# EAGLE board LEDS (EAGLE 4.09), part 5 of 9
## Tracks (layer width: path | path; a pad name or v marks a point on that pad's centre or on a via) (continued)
N$X.358  (via drill 0.2)  (1 unrouted) (continued)
  Bottom 0.2: 115.32,46.92 115.87,46.37
  other vias: 115.92,46.28
N$X.359  (via drill 0.2)  (1 unrouted)
  Bottom 0.2: 56.79,39.04 57.33,38.49
  other vias: 57.39,38.4
N$X.360  (via drill 0.2)  (1 unrouted)
  Bottom 0.2: 55.06,39.04 55.6,38.49
  other vias: 55.66,38.4
N$X.361  (via drill 0.2)  (1 unrouted)
  Bottom 0.2: 53.24,39.08 53.78,38.54
  other vias: 53.84,38.44
N$X.362  (via drill 0.2)  (1 unrouted)
  Bottom 0.2: 51.39,39.08 51.94,38.54
  other vias: 51.99,38.44
N$X.363  (via drill 0.2)  (1 unrouted)
  Bottom 0.2: 49.62,39.08 50.16,38.54
  other vias: 50.22,38.44
N$X.364  (via drill 0.2)  (1 unrouted)
  Bottom 0.2: 47.84,39.13 48.39,38.58
  other vias: 48.44,38.49
N$X.365  (via drill 0.2)  (1 unrouted)
  Bottom 0.2: 45.98,39.06 46.52,38.51
  other vias: 46.57,38.42
N$X.366  (via drill 0.2)  (1 unrouted)
  Bottom 0.2: 44.22,39.04 44.77,38.49
  other vias: 44.82,38.4
N$X.367  (via drill 0.2)  (1 unrouted)
  Bottom 0.2: 40.67,36.38 41.22,35.84
  other vias: 41.27,35.75
N$X.368  (via drill 0.2)  (1 unrouted)
  Bottom 0.2: 42.38,36.47 42.92,35.93
  other vias: 42.98,35.84
N$X.369  (via drill 0.2)  (1 unrouted)
  Bottom 0.2: 44.22,36.47 44.77,35.93
  other vias: 44.82,35.84
N$X.370  (via drill 0.2)  (1 unrouted)
  Bottom 0.2: 45.98,36.43 46.52,35.88
  other vias: 46.57,35.79
N$X.371  (via drill 0.2)  (1 unrouted)
  Bottom 0.2: 47.82,36.41 48.37,35.86
  other vias: 48.42,35.77
N$X.372  (via drill 0.2)  (1 unrouted)
  Bottom 0.2: 49.59,36.43 50.14,35.88
  other vias: 50.19,35.79
N$X.373  (via drill 0.2)  (1 unrouted)
  Bottom 0.2: 51.39,36.45 51.94,35.91
  other vias: 51.99,35.81
N$X.374  (via drill 0.2)  (1 unrouted)
  Bottom 0.2: 53.21,36.45 53.76,35.91
  other vias: 53.81,35.81
N$X.375  (via drill 0.2)  (1 unrouted)
  Bottom 0.2: 98.04,33.18 97.41,33.81 97.38,33.81
  other vias: 98.02,33.19
N$X.376  (via drill 0.2)  (1 unrouted)
  Bottom 0.2: 98.02,35.83 97.38,36.46 97.22,36.46
  other vias: 98.03,35.85
N$X.377  (via drill 0.2)  (1 unrouted)
  Bottom 0.2: 98.09,38.48 97.53,39.05 97.15,39.05
  other vias: 98.09,38.44
N$X.378  (via drill 0.2)  (2 unrouted)
  Bottom 0.2: 97.48,41.6 97.42,41.78 | 98.05,41.08 97.41,41.73 97.07,41.73
  other vias: 98.09,41.05
N$X.379  (via drill 0.2)  (1 unrouted)
  Bottom 0.2: v97.98,43.66 97.98,43.71 97.42,44.43
N$X.380  (via drill 0.2)  (1 unrouted)
  Bottom 0.2: 98.06,46.21 97.43,46.85 97.09,46.85
  other vias: 98.03,46.21
N$X.381  (via drill 0.2)  (1 unrouted)
  Bottom 0.2: 55.01,36.41 55.56,35.86
  other vias: 55.61,35.77
N$X.382  (via drill 0.2)  (1 unrouted)
  Bottom 0.2: 56.81,36.45 57.36,35.91
  other vias: 57.41,35.81
N$X.383  (via drill 0.2)  (1 unrouted)
  Bottom 0.2: 40.58,33.82 41.13,33.28
  other vias: 41.18,33.18
N$X.384  (via drill 0.2)  (1 unrouted)
  Bottom 0.2: 42.42,33.8 42.97,33.25
  other vias: 43.02,33.16
N$X.385  (via drill 0.2)  (1 unrouted)
  Bottom 0.2: 44.18,33.78 44.72,33.23
  other vias: 44.78,33.14
N$X.386  (via drill 0.2)  (1 unrouted)
  Bottom 0.2: 46,33.8 46.54,33.25
  other vias: 46.6,33.16
N$X.387  (via drill 0.2)  (1 unrouted)
  Bottom 0.2: 47.82,33.82 48.37,33.28
  other vias: 48.42,33.18
N$X.388  (via drill 0.2)  (1 unrouted)
  Bottom 0.2: 49.62,33.78 50.16,33.23
  other vias: 50.22,33.14
N$X.389  (via drill 0.2)  (1 unrouted)
  Bottom 0.2: 51.33,33.8 51.87,33.25
  other vias: 51.92,33.16
N$X.390  (via drill 0.2)  (1 unrouted)
  Bottom 0.2: 53.21,33.82 53.76,33.28
  other vias: 53.81,33.18
N$X.391  (via drill 0.2)  (1 unrouted)
  Bottom 0.2: 55.03,33.8 55.58,33.25
  other vias: 55.63,33.16
N$X.392  (via drill 0.2)  (1 unrouted)
  Bottom 0.2: 56.81,33.82 57.36,33.28
  other vias: 57.41,33.18
N$X.393  (via drill 0.2)  (1 unrouted)
  Bottom 0.2: 56.83,31.26 57.38,30.71
  other vias: 57.43,30.62
N$X.394  (via drill 0.2)  (1 unrouted)
  Bottom 0.2: 55.01,31.26 55.56,30.71
  other vias: 55.61,30.62
N$X.395  (via drill 0.2)  (1 unrouted)
  Bottom 0.2: 53.21,31.28 53.76,30.74
  other vias: 53.81,30.64
N$X.396  (via drill 0.2)  (1 unrouted)
  Bottom 0.2: 51.44,31.19 51.98,30.65
  other vias: 52.04,30.55
N$X.397  (via drill 0.2)  (1 unrouted)
  Bottom 0.2: 49.62,31.24 50.16,30.69
  other vias: 50.22,30.6
N$X.398  (via drill 0.2)  (1 unrouted)
  Bottom 0.2: 47.8,31.26 48.34,30.71
  other vias: 48.39,30.62
N$X.399  (via drill 0.2)  (1 unrouted)
  Bottom 0.2: 46,31.26 46.54,30.71
  other vias: 46.6,30.62
N$X.400  (via drill 0.2)  (1 unrouted)
  Bottom 0.2: 44.22,31.26 44.77,30.71
  other vias: 44.82,30.62
N$X.401  (via drill 0.2)  (1 unrouted)
  Bottom 0.2: 42.45,31.3 42.99,30.76
  other vias: 43.05,30.67
N$X.402  (via drill 0.2)  (1 unrouted)
  Bottom 0.2: 40.65,31.24 41.19,30.69
  other vias: 41.25,30.6
N$X.403  (via drill 0.2)  (1 unrouted)
  Bottom 0.2: 101.57,25.14 101.03,25.68 100.67,25.68
  other vias: 101.53,25.12
N$X.404  (via drill 0.2)  (1 unrouted)
  Bottom 0.2: 40.63,28.54 41.17,28
  other vias: 41.23,27.9
N$X.405  (via drill 0.2)  (1 unrouted)
  Bottom 0.2: 42.45,28.54 42.99,28
  other vias: 43.05,27.9
N$X.406  (via drill 0.2)  (1 unrouted)
  Bottom 0.2: 96.28,33.16 95.49,33.95 95.4,33.95
  other vias: 96.31,33.15
N$X.407  (via drill 0.2)  (1 unrouted)
  Bottom 0.2: 96.3,35.8 95.72,36.38 95.59,36.38
  other vias: 96.34,35.83
N$X.408  (via drill 0.2)  (1 unrouted)
  Bottom 0.2: 96.36,38.43 95.74,39.05 95.53,39.05
  other vias: 96.37,38.41
N$X.409  (via drill 0.2)  (1 unrouted)
  Bottom 0.2: 96.28,41.01 95.59,41.69 95.59,41.82
  other vias: 96.3,41.04
N$X.410  (via drill 0.2)
  Bottom 0.2: 96.32,43.73 v96.29,43.62 95.77,44.33
N$X.411  (via drill 0.2)  (1 unrouted)
  Bottom 0.2: 96.3,46.17 95.62,46.85 95.22,46.85
  other vias: 96.33,46.2
N$X.412  (via drill 0.2)  (1 unrouted)
  Bottom 0.2: 44.22,28.56 44.77,28.02
  other vias: 44.82,27.93
N$X.413  (via drill 0.2)  (1 unrouted)
  Bottom 0.2: 46,28.54 46.54,28
  other vias: 46.6,27.9
N$X.414  (via drill 0.2)  (1 unrouted)
  Bottom 0.2: 47.75,28.56 48.3,28.02
  other vias: 48.35,27.93
N$X.415  (via drill 0.2)  (1 unrouted)
  Bottom 0.2: 49.59,28.5 50.14,27.95
  other vias: 50.19,27.86
N$X.416  (via drill 0.2)  (1 unrouted)
  Bottom 0.2: 51.46,28.54 52.01,28
  other vias: 52.06,27.9
N$X.417  (via drill 0.2)  (1 unrouted)
  Bottom 0.2: 53.19,28.52 53.74,27.97
  other vias: 53.79,27.88
N$X.418  (via drill 0.2)  (1 unrouted)
  Bottom 0.2: 55.06,28.56 55.6,28.02
  other vias: 55.66,27.93
N$X.419  (via drill 0.2)  (1 unrouted)
  Bottom 0.2: 56.74,28.54 57.29,28
  other vias: 57.34,27.9
N$X.420  (via drill 0.2)  (1 unrouted)
  Bottom 0.2: 56.83,25.75 57.38,25.21
  other vias: 57.43,25.11
N$X.421  (via drill 0.2)  (1 unrouted)
  Bottom 0.2: 54.97,25.75 55.51,25.21
  other vias: 55.56,25.11
N$X.422  (via drill 0.2)  (1 unrouted)
  Bottom 0.2: 53.19,25.73 53.74,25.19
  other vias: 53.79,25.09
N$X.423  (via drill 0.2)  (1 unrouted)
  Bottom 0.2: 51.42,25.73 51.96,25.19
  other vias: 52.01,25.09
N$X.424  (via drill 0.2)  (1 unrouted)
  Bottom 0.2: 49.62,25.73 50.16,25.19
  other vias: 50.22,25.09
N$X.425  (via drill 0.2)  (1 unrouted)
  Bottom 0.2: 47.82,25.73 48.37,25.19
  other vias: 48.42,25.09
N$X.426  (via drill 0.2)  (1 unrouted)
  Bottom 0.2: 45.98,25.69 46.52,25.14
  other vias: 46.57,25.05
N$X.427  (via drill 0.2)  (1 unrouted)
  Bottom 0.2: 44.25,25.71 44.79,25.16
  other vias: 44.84,25.07
N$X.428  (via drill 0.2)  (1 unrouted)
  Bottom 0.2: 42.42,25.66 42.97,25.12
  other vias: 43.02,25.03
N$X.429  (via drill 0.2)  (1 unrouted)
  Bottom 0.2: 40.6,25.71 41.15,25.16
  other vias: 41.2,25.07
N$X.430  (via drill 0.2)  (1 unrouted)
  Bottom 0.2: 40.65,23.12 41.19,22.58
  other vias: 41.25,22.49
N$X.431  (via drill 0.2)  (1 unrouted)
  Bottom 0.2: 42.45,23.1 42.99,22.56
  other vias: 43.05,22.46
N$X.432  (via drill 0.2)  (1 unrouted)
  Bottom 0.2: 44.2,23.12 44.75,22.58
  other vias: 44.8,22.49
N$X.433  (via drill 0.2)  (1 unrouted)
  Bottom 0.2: 45.93,23.1 46.48,22.56
  other vias: 46.53,22.46
N$X.434  (via drill 0.2)  (1 unrouted)
  Bottom 0.2: 47.8,23.12 48.34,22.58
  other vias: 48.39,22.49
N$X.435  (via drill 0.2)  (1 unrouted)
  Bottom 0.2: 49.57,23.1 50.12,22.56
  other vias: 50.17,22.46
N$X.436  (via drill 0.2)  (1 unrouted)
  Bottom 0.2: 51.35,23.17 51.89,22.62
  other vias: 51.95,22.53
N$X.437  (via drill 0.2)  (1 unrouted)
  Bottom 0.2: 94.65,33.17 94.12,33.7 93.87,33.7
  other vias: 94.59,33.19
N$X.438  (via drill 0.2)  (1 unrouted)
  Bottom 0.2: 94.57,35.84 94.06,36.34 93.96,36.34
  other vias: 94.59,35.83
N$X.439  (via drill 0.2)  (1 unrouted)
  Bottom 0.2: 94.55,38.44 93.91,39.08 93.78,39.08
  other vias: 94.59,38.44
N$X.440  (via drill 0.2)
  other vias: 94.54,41.05
N$X.441  (via drill 0.2)  (1 unrouted)
  Bottom 0.2: 94.57,43.83 94.57,43.73 94.02,44.28
  other vias: 94.59,43.64
N$X.442  (via drill 0.2)
  Bottom 0.2: 94.02,46.88 v94.58,46.17
N$X.443  (via drill 0.2)  (1 unrouted)
  Bottom 0.2: 53.19,23.15 53.74,22.6
  other vias: 53.79,22.51
N$X.444  (via drill 0.2)  (1 unrouted)
  Bottom 0.2: 54.95,23.12 55.49,22.58
  other vias: 55.54,22.49
N$X.445  (via drill 0.2)  (1 unrouted)
  Bottom 0.2: 56.77,23.15 57.31,22.6
  other vias: 57.36,22.51
N$X.446  (via drill 0.2)  (1 unrouted)
  Bottom 0.2: 40.58,20.52 41.13,19.97
  other vias: 41.18,19.88
N$X.447  (via drill 0.2)  (1 unrouted)
  Bottom 0.2: 42.4,20.54 42.95,19.99
  other vias: 43,19.9
N$X.448  (via drill 0.2)  (1 unrouted)
  Bottom 0.2: 44.27,20.56 44.81,20.02
  other vias: 44.87,19.92
N$X.449  (via drill 0.2)  (1 unrouted)
  Bottom 0.2: 45.95,20.56 46.5,20.02
  other vias: 46.55,19.92
N$X.450  (via drill 0.2)  (1 unrouted)
  Bottom 0.2: 47.75,20.56 48.3,20.02
  other vias: 48.35,19.92
N$X.451  (via drill 0.2)  (1 unrouted)
  Bottom 0.2: 49.48,20.54 50.03,19.99
  other vias: 50.08,19.9
N$X.452  (via drill 0.2)  (1 unrouted)
  Bottom 0.2: 51.42,20.52 51.96,19.97
  other vias: 52.01,19.88
N$X.453  (via drill 0.2)  (1 unrouted)
  Bottom 0.2: 53.15,20.56 53.69,20.02
  other vias: 53.74,19.92
N$X.454  (via drill 0.2)  (1 unrouted)
  Bottom 0.2: 54.99,20.56 55.53,20.02
  other vias: 55.59,19.92
N$X.455  (via drill 0.2)  (1 unrouted)
  Bottom 0.2: 56.79,20.52 57.33,19.97
  other vias: 57.39,19.88
N$X.456  (via drill 0.2)  (1 unrouted)
  Bottom 0.2: 40.63,17.98 41.17,17.43
  other vias: 41.23,17.34
N$X.457  (via drill 0.2)  (1 unrouted)
  Bottom 0.2: 42.4,17.98 42.95,17.43
  other vias: 43,17.34
N$X.458  (via drill 0.2)  (1 unrouted)
  Bottom 0.2: 44.22,18.04 44.77,17.5
  other vias: 44.82,17.41
N$X.459  (via drill 0.2)  (1 unrouted)
  Bottom 0.2: 45.98,17.95 46.52,17.41
  other vias: 46.57,17.32
N$X.460  (via drill 0.2)  (1 unrouted)
  Bottom 0.2: 47.8,17.93 48.34,17.39
  other vias: 48.39,17.29
N$X.461  (via drill 0.2)  (1 unrouted)
  Bottom 0.2: 49.55,17.98 50.09,17.43
  other vias: 50.15,17.34
N$X.462  (via drill 0.2)  (1 unrouted)
  Bottom 0.2: 51.44,17.98 51.98,17.43
  other vias: 52.04,17.34
N$X.463  (via drill 0.2)  (1 unrouted)
  Bottom 0.2: 53.17,17.98 53.71,17.43
  other vias: 53.77,17.34
N$X.464  (via drill 0.2)  (1 unrouted)
  Bottom 0.2: 55.01,18.02 55.56,17.48
  other vias: 55.61,17.38
N$X.465  (via drill 0.2)  (1 unrouted)
  Bottom 0.2: 56.79,17.93 57.33,17.39
  other vias: 57.39,17.29
N$X.466  (via drill 0.2)  (1 unrouted)
  Bottom 0.2: 44.18,15.41 44.72,14.87
  other vias: 44.78,14.78
N$X.467  (via drill 0.2)  (1 unrouted)
  Bottom 0.2: 46,15.44 46.54,14.89
  other vias: 46.6,14.8
N$X.468  (via drill 0.2)  (1 unrouted)
  Bottom 0.2: 92.8,33.18 92.22,33.75 92.22,33.95
  other vias: 92.82,33.15
N$X.469  (via drill 0.2)  (1 unrouted)
  Bottom 0.2: 92.83,35.75 92.28,36.29 92.28,36.64
  other vias: 92.8,35.78
N$X.470  (via drill 0.2)  (1 unrouted)
  Bottom 0.2: 92.83,38.42 92.29,38.95 92.29,39.14
  other vias: 92.81,38.4
N$X.471  (via drill 0.2)  (1 unrouted)
  Bottom 0.2: 92.88,41.04 92.24,41.68 92.24,41.7
  other vias: 92.79,41.05
N$X.472  (via drill 0.2)  (1 unrouted)
  Bottom 0.2: 92.27,44.23 92.82,43.73
  other vias: 92.75,43.64
N$X.473  (via drill 0.2)
  Bottom 0.2: v92.92,46.18 92.22,46.88
N$X.474  (via drill 0.2)  (1 unrouted)
  Bottom 0.2: 47.77,15.46 48.32,14.91
  other vias: 48.37,14.82
N$X.475  (via drill 0.2)  (1 unrouted)
  Bottom 0.2: 49.64,15.46 50.19,14.91
  other vias: 50.24,14.82
N$X.476  (via drill 0.2)  (1 unrouted)
  Bottom 0.2: 51.37,15.41 51.92,14.87
  other vias: 51.97,14.78
N$X.477  (via drill 0.2)  (1 unrouted)
  Bottom 0.2: 53.15,15.44 53.69,14.89
  other vias: 53.74,14.8
N$X.478  (via drill 0.2)  (1 unrouted)
  Bottom 0.2: 55.01,15.41 55.56,14.87
  other vias: 55.61,14.78
N$X.479  (via drill 0.2)  (1 unrouted)
  Bottom 0.2: 56.83,15.46 57.38,14.91
  other vias: 57.43,14.82
N$X.480  (via drill 0.2)  (1 unrouted)
  Bottom 0.2: 46.09,12.81 46.63,12.26
  other vias: 46.69,12.17
N$X.481  (via drill 0.2)  (1 unrouted)
  Bottom 0.2: 47.82,12.85 48.37,12.31
  other vias: 48.42,12.21
N$X.482  (via drill 0.2)  (1 unrouted)
  Bottom 0.2: 49.59,12.83 50.14,12.29
  other vias: 50.19,12.19
N$X.483  (via drill 0.2)  (1 unrouted)
  Bottom 0.2: 51.44,12.83 51.98,12.29
  other vias: 52.04,12.19
N$X.484  (via drill 0.2)  (1 unrouted)
  Bottom 0.2: 53.26,12.83 53.8,12.29
  other vias: 53.86,12.19
N$X.485  (via drill 0.2)  (1 unrouted)
  Bottom 0.2: 55.06,12.85 55.6,12.31
  other vias: 55.66,12.21
N$X.486  (via drill 0.2)  (1 unrouted)
  Bottom 0.2: 56.86,12.85 57.4,12.31
  other vias: 57.45,12.21
N$X.487  (via drill 0.2)  (1 unrouted)
  Bottom 0.2: 56.81,10.22 57.36,9.68
  other vias: 57.41,9.58
N$X.488  (via drill 0.2)  (1 unrouted)
  Bottom 0.2: 55.01,10.24 55.56,9.7
  other vias: 55.61,9.61
N$X.489  (via drill 0.2)  (1 unrouted)
  Bottom 0.2: 53.21,10.22 53.76,9.68
  other vias: 53.81,9.58
N$X.490  (via drill 0.2)  (1 unrouted)
  Bottom 0.2: 51.44,10.22 51.98,9.68
  other vias: 52.04,9.58
N$X.491  (via drill 0.2)  (1 unrouted)
  Bottom 0.2: 49.59,10.24 50.14,9.7
  other vias: 50.19,9.61
N$X.492  (via drill 0.2)  (1 unrouted)
  Bottom 0.2: 47.84,10.2 48.39,9.65
  other vias: 48.44,9.56
N$X.493  (via drill 0.2)  (1 unrouted)
  Bottom 0.2: 46.04,10.24 46.59,9.7
  other vias: 46.64,9.61
N$X.494  (via drill 0.2)  (1 unrouted)
  Bottom 0.2: 46.04,7.64 46.59,7.09
  other vias: 46.64,7
N$X.495  (via drill 0.2)  (1 unrouted)
  Bottom 0.2: 47.82,7.57 48.37,7.03
  other vias: 48.42,6.93
N$X.496  (via drill 0.2)  (1 unrouted)
  Bottom 0.2: 49.53,7.62 50.07,7.07
  other vias: 50.13,6.98
N$X.497  (via drill 0.2)  (1 unrouted)
  Bottom 0.2: 51.44,7.57 51.98,7.03
  other vias: 52.04,6.93
N$X.498  (via drill 0.2)  (1 unrouted)
  Bottom 0.2: 53.24,7.62 53.78,7.07
  other vias: 53.84,6.98
N$X.499  (via drill 0.2)  (1 unrouted)
  Bottom 0.2: 91.14,33.16 90.39,33.91 90.35,33.91
  other vias: 91.06,33.2
N$X.500  (via drill 0.2)  (1 unrouted)
  Bottom 0.2: 55.06,7.55 55.6,7
  other vias: 55.66,6.91
N$X.501
  Bottom 0.2: 91.08,38.44 90.32,39.21 89.74,39.21
N$X.502  (via drill 0.2)
  Bottom 0.2: v91.07,41.03 90.42,41.68
N$X.503  (via drill 0.2)  (1 unrouted)
  Bottom 0.2: 91.03,43.66 90.36,44.33 90.2,44.33
  other vias: 91.07,43.63
N$X.504  (via drill 0.2)
  Bottom 0.2: v91.07,46.23 90.37,46.93
N$X.505  (via drill 0.2)  (1 unrouted)
  Bottom 0.2: 56.86,7.62 57.4,7.07
  other vias: 57.45,6.98
N$X.506  (via drill 0.2)  (1 unrouted)
  Bottom 0.2: 45.98,4.92 46.52,4.37
  other vias: 46.57,4.28
N$X.507  (via drill 0.2)  (1 unrouted)
  Bottom 0.2: 47.82,4.92 48.37,4.37
  other vias: 48.42,4.28
N$X.508  (via drill 0.2)  (1 unrouted)
  Bottom 0.2: 49.59,4.9 50.14,4.35
  other vias: 50.19,4.26
N$X.509  (via drill 0.2)  (1 unrouted)
  Bottom 0.2: 51.46,4.92 52.01,4.37
  other vias: 52.06,4.28
N$X.510  (via drill 0.2)  (1 unrouted)
  Bottom 0.2: 53.19,4.94 53.74,4.4
  other vias: 53.79,4.3
N$X.511  (via drill 0.2)  (1 unrouted)
  Bottom 0.2: 55.03,4.94 55.58,4.4
  other vias: 55.63,4.3
N$X.512  (via drill 0.2)  (1 unrouted)
  Bottom 0.2: 56.81,4.94 57.36,4.4
  other vias: 57.41,4.3
N$X.513  (via drill 0.2)  (1 unrouted)
  Bottom 0.2: 113.15,46.9 113.69,46.36
  other vias: 113.75,46.26
N$X.514  (via drill 0.2)  (2 unrouted)
  Top 0.8: 48.45,1.71 48.41,85.06
  Bottom 0.2: 47.84,2.31 48.39,1.77
  other vias: 48.44,1.67
N$X.515  (via drill 0.2)  (1 unrouted)
  Bottom 0.2: 113.17,44.31 113.72,43.77
  other vias: 113.77,43.67
N$X.516  (via drill 0.2)  (2 unrouted)
  Top 0.8: 52.06,1.55 52.06,84.21 52.06,84.95
  Bottom 0.2: 51.46,2.36 52.01,1.81
  other vias: 52.06,1.72
N$X.517  (via drill 0.2)  (1 unrouted)
  Bottom 0.2: 113.23,41.72 113.77,41.17
  other vias: 113.83,41.08
N$X.518  (via drill 0.2)  (2 unrouted)
  Top 0.8: 55.55,1.71 55.55,84.24 55.56,84.94
  Bottom 0.2: 54.97,2.31 55.51,1.77
  other vias: 55.56,1.67
N$X.519  (via drill 0.2)  (1 unrouted)
  Bottom 0.2: 113.15,39.08 113.69,38.53
  other vias: 113.75,38.44
N$X.520  (via drill 0.2)  (1 unrouted)
  Bottom 0.2: 58.61,4.9 59.15,4.35
  other vias: 59.21,4.26
N$X.521  (via drill 0.2)  (2 unrouted)
  Top 0.5: 59.3,1.7 59.21,1.7
  Top 0.8: 59.3,1.7 59.3,84.82
  Bottom 0.2: 58.68,2.36 59.22,1.81
  other vias: 59.27,1.72
N$X.522  (via drill 0.2)  (1 unrouted)
  Bottom 0.2: 40.65,75.63 41.2,75.09
  other vias: 41.25,75
N$X.523  (via drill 0.2)  (1 unrouted)
  Bottom 0.2: 113.07,36.43 113.61,35.89
  other vias: 113.66,35.79
N$X.524  (via drill 0.2)  (1 unrouted)
  Bottom 0.2: 44.22,75.56 44.77,75.01
  other vias: 44.82,74.92
N$X.525  (via drill 0.2)  (1 unrouted)
  Bottom 0.2: 44.22,73.05 44.77,72.5
  other vias: 44.82,72.41
N$X.526  (via drill 0.2)  (1 unrouted)
  Bottom 0.2: 42.36,73.05 42.9,72.5
  other vias: 42.96,72.41
N$X.527  (via drill 0.2)  (1 unrouted)
  Bottom 0.2: 40.63,73.08 41.17,72.53
  other vias: 41.23,72.44
N$X.528  (via drill 0.2)  (1 unrouted)
  Bottom 0.2: 40.63,70.49 41.17,69.95
  other vias: 41.23,69.86
N$X.529  (via drill 0.2)  (1 unrouted)
  Bottom 0.2: 42.44,70.49 42.98,69.95
  other vias: 43.03,69.86
N$X.530  (via drill 0.2)  (1 unrouted)
  Bottom 0.2: 89.26,33.18 88.67,33.77 88.37,33.77
  other vias: 89.28,33.19
N$X.531  (via drill 0.2)  (1 unrouted)
  Bottom 0.2: 44.24,70.44 44.79,69.9
  other vias: 44.84,69.8
N$X.532  (via drill 0.2)  (1 unrouted)
  Bottom 0.2: v89.34,38.42 88.8,38.96 88.61,38.96
N$X.533  (via drill 0.2)
  Bottom 0.2: 88.77,41.78 89.27,41.08
  Bottom 0.5: 89.27,41.08 v89.3,41.04
N$X.534  (via drill 0.2)
  Bottom 0.2: 89.32,43.83 v89.22,43.65 88.82,44.18
N$X.535  (via drill 0.2)  (1 unrouted)
  Bottom 0.2: 89.24,46.17 88.36,47.05 88.31,47.09
  other vias: 89.23,46.19
N$X.536  (via drill 0.2)  (1 unrouted)
  Bottom 0.2: 46.05,70.49 46.6,69.95
  other vias: 46.65,69.86
N$X.537  (via drill 0.2)  (1 unrouted)
  Bottom 0.2: 47.84,70.49 48.38,69.95
  other vias: 48.44,69.86
N$X.538  (via drill 0.2)  (1 unrouted)
  Bottom 0.2: 49.62,70.42 50.16,69.87
  other vias: 50.22,69.78
N$X.539  (via drill 0.2)  (1 unrouted)
  Bottom 0.2: 51.45,70.47 52,69.92
  other vias: 52.05,69.83
N$X.540  (via drill 0.2)  (1 unrouted)
  Bottom 0.2: 53.26,70.42 53.81,69.87
  other vias: 53.86,69.78
N$X.541  (via drill 0.2)  (1 unrouted)
  Bottom 0.2: 40.63,67.81 41.17,67.26
  other vias: 41.23,67.17
N$X.542  (via drill 0.2)  (1 unrouted)
  Bottom 0.2: 40.63,65.2 41.17,64.65
  other vias: 41.23,64.56
N$X.543  (via drill 0.2)  (1 unrouted)
  Bottom 0.2: 42.96,64.68 42.41,65.22
  other vias: 43.01,64.59
N$X.544  (via drill 0.2)  (1 unrouted)
  Bottom 0.2: 42.44,67.81 42.98,67.26
  other vias: 43.03,67.17
N$X.545  (via drill 0.2)  (1 unrouted)
  Bottom 0.2: 44.22,67.83 44.77,67.29
  other vias: 44.82,67.19
N$X.546  (via drill 0.2)  (1 unrouted)
  Bottom 0.2: 44.79,64.68 44.24,65.22
  other vias: 44.84,64.59
N$X.547  (via drill 0.2)  (1 unrouted)
  Bottom 0.2: 46.03,67.86 46.57,67.31
  other vias: 46.63,67.22
N$X.548  (via drill 0.2)  (1 unrouted)
  Bottom 0.2: 46.55,64.7 46,65.25
  other vias: 46.6,64.61
N$X.549  (via drill 0.2)  (1 unrouted)
  Bottom 0.2: 48.33,64.65 47.78,65.2
  other vias: 48.38,64.56
N$X.550  (via drill 0.2)  (1 unrouted)
  Bottom 0.2: 48.33,67.21 47.78,67.75
  other vias: 48.38,67.12
N$X.551  (via drill 0.2)  (1 unrouted)
  Bottom 0.2: 50.16,67.18 49.62,67.73
  other vias: 50.22,67.09
N$X.552  (via drill 0.2)  (1 unrouted)
  Bottom 0.2: 50.16,64.63 49.62,65.17
  other vias: 50.22,64.53
N$X.553  (via drill 0.2)  (1 unrouted)
  Bottom 0.2: 51.97,67.23 51.43,67.78
  other vias: 52.03,67.14
N$X.554  (via drill 0.2)  (1 unrouted)
  Bottom 0.2: 51.97,64.63 51.43,65.17
  other vias: 52.03,64.53
N$X.555  (via drill 0.2)  (1 unrouted)
  Bottom 0.2: 53.18,67.78 53.73,67.23
  other vias: 53.78,67.14
N$X.556  (via drill 0.2)  (1 unrouted)
  Bottom 0.2: 53.18,65.2 53.73,64.65
  other vias: 53.78,64.56
N$X.557  (via drill 0.2)  (1 unrouted)
  Bottom 0.2: 55.49,64.65 54.94,65.2
  other vias: 55.54,64.56
N$X.558  (via drill 0.2)  (1 unrouted)
  Bottom 0.2: 55.07,67.81 55.62,67.26
  other vias: 55.67,67.17
N$X.559  (via drill 0.2)  (1 unrouted)
  Bottom 0.2: 56.75,67.83 57.3,67.29
  other vias: 57.35,67.19
N$X.560  (via drill 0.2)  (1 unrouted)
  Bottom 0.2: 57.37,64.65 56.83,65.2
  other vias: 57.42,64.56
N$X.561  (via drill 0.2)  (1 unrouted)
  Bottom 0.2: 87.52,33.18 86.71,33.99 86.71,34.05
  other vias: 87.52,33.2
N$X.562  (via drill 0.2)  (1 unrouted)
  Bottom 0.2: 87.61,35.81 86.94,36.47 86.59,36.47
  other vias: 87.57,35.83
N$X.563  (via drill 0.2)  (1 unrouted)
  Bottom 0.2: 87.45,38.4 86.61,39.24 86.57,39.24
  other vias: 87.5,38.42
N$X.564  (via drill 0.2)
  Bottom 0.2: v87.57,41.03 87.42,41.08 86.82,41.68
N$X.565  (via drill 0.2)  (1 unrouted)
  Bottom 0.2: 87.47,43.83 87.47,43.68 86.92,44.23
  other vias: 87.53,43.68
N$X.566  (via drill 0.2)  (1 unrouted)
  Bottom 0.2: v87.58,46.22 86.92,46.88 86.69,46.88
N$X.567  (via drill 0.2)  (1 unrouted)
  Bottom 0.2: 58.59,7.63 59.14,7.08
  other vias: 59.19,6.99
N$X.568  (via drill 0.2)  (1 unrouted)
  Bottom 0.2: 60.41,7.57 60.96,7.02
  other vias: 61.01,6.93
N$X.569  (via drill 0.2)  (1 unrouted)
  Bottom 0.2: 62.21,7.63 62.76,7.08
  other vias: 62.81,6.99
N$X.570  (via drill 0.2)  (1 unrouted)
  Bottom 0.2: 63.98,7.59 64.52,7.04
  other vias: 64.57,6.95
N$X.571  (via drill 0.2)  (1 unrouted)
  Bottom 0.2: 65.72,7.59 66.26,7.04
  other vias: 66.31,6.95
N$X.572  (via drill 0.2)  (1 unrouted)
  Bottom 0.2: 65.7,4.96 66.24,4.41
  other vias: 66.3,4.32
N$X.573  (via drill 0.2)  (1 unrouted)
  Bottom 0.2: 63.98,4.92 64.52,4.37
  other vias: 64.57,4.28
N$X.574  (via drill 0.2)  (1 unrouted)
  Bottom 0.2: 62.17,4.92 62.72,4.37
  other vias: 62.77,4.28
N$X.575  (via drill 0.2)  (1 unrouted)
  Bottom 0.2: 60.41,4.9 60.96,4.35
  other vias: 61.01,4.26
N$X.576  (via drill 0.2)  (2 unrouted)
  Top 0.8: 61.01,1.61 61.01,84.56 60.98,84.85
  Bottom 0.2: 60.43,2.33 60.98,1.78
  other vias: 61.03,1.69
N$X.577  (via drill 0.2)  (1 unrouted)
  Bottom 0.2: 62.21,2.35 62.76,1.8
  other vias: 62.81,1.71
N$X.578  (via drill 0.2)  (2 unrouted)
  Top 0.8: 64.61,1.52 64.61,84.65
  Bottom 0.2: 64.02,2.29 64.56,1.74
  other vias: 64.61,1.65
N$X.579  (via drill 0.2)  (2 unrouted)
  Top 0.5: 66.5,1.7 66.41,1.61
  Top 0.8: 66.5,1.7 66.5,84.92
  Bottom 0.2: 65.7,2.31 66.24,1.76
  other vias: 66.3,1.67
N$X.580  (via drill 0.2)  (1 unrouted)
  Bottom 0.2: 58.61,10.12 59.16,9.58
  other vias: 59.21,9.48
N$X.581  (via drill 0.2)  (1 unrouted)
  Bottom 0.2: 60.43,10.26 60.98,9.71
  other vias: 61.03,9.62
N$X.582  (via drill 0.2)  (1 unrouted)
  Bottom 0.2: 62.17,10.24 62.72,9.7
  other vias: 62.77,9.6
N$X.583  (via drill 0.2)  (1 unrouted)
  Bottom 0.2: 63.96,10.22 64.5,9.67
  other vias: 64.55,9.58
N$X.584  (via drill 0.2)  (1 unrouted)
  Bottom 0.2: 65.76,10.2 66.3,9.66
  other vias: 66.36,9.56
N$X.585  (via drill 0.2)  (1 unrouted)
  Bottom 0.2: 58.55,12.78 59.1,12.23
  other vias: 59.15,12.14
N$X.586  (via drill 0.2)  (1 unrouted)
  Bottom 0.2: 60.45,12.82 61,12.27
  other vias: 61.05,12.18
N$X.587  (via drill 0.2)  (1 unrouted)
  Bottom 0.2: 62.23,12.78 62.78,12.23
  other vias: 62.83,12.14
N$X.588  (via drill 0.2)  (1 unrouted)
  Bottom 0.2: 64.02,12.78 64.56,12.23
  other vias: 64.61,12.14
N$X.589  (via drill 0.2)  (1 unrouted)
  Bottom 0.2: 65.76,12.78 66.3,12.23
  other vias: 66.36,12.14
N$X.590  (via drill 0.2)  (1 unrouted)
  Bottom 0.2: 65.68,15.43 66.22,14.89
  other vias: 66.28,14.79
N$X.591  (via drill 0.2)  (1 unrouted)
  Bottom 0.2: 63.98,15.43 64.52,14.89
  other vias: 64.57,14.79
N$X.592  (via drill 0.2)  (1 unrouted)
  Bottom 0.2: 85.79,33.11 85.05,33.84 85.05,33.86
  other vias: 85.78,33.18
N$X.593  (via drill 0.2)  (1 unrouted)
  Bottom 0.2: 62.2,15.39 62.74,14.85
  other vias: 62.79,14.75
N$X.594  (via drill 0.2)  (1 unrouted)
  Bottom 0.2: 85.86,38.47 85.21,39.11 85.08,39.11
  other vias: 85.78,38.43
N$X.595  (via drill 0.2)
  Bottom 0.2: v85.82,41.03 85.67,41.18 85.27,41.78
N$X.596  (via drill 0.2)  (1 unrouted)
  Bottom 0.2: 85.72,43.63 85.49,43.77 85.04,44.52
  other vias: 85.77,43.64
N$X.597  (via drill 0.2)
  Bottom 0.2: v85.77,46.23 85.67,46.18 85.22,47.03
N$X.598  (via drill 0.2)  (1 unrouted)
  Bottom 0.2: 60.41,15.39 60.96,14.85
  other vias: 61.01,14.75
N$X.599  (via drill 0.2)  (1 unrouted)
  Bottom 0.2: 82.45,59.43 81.91,59.97 81.56,59.97
  other vias: 82.41,59.41
N$X.600  (via drill 0.2)  (1 unrouted)
  Bottom 0.2: 58.63,15.43 59.18,14.89
  other vias: 59.23,14.79
N$X.601  (via drill 0.2)  (1 unrouted)
  Bottom 0.2: 58.67,17.96 59.22,17.42
  other vias: 59.27,17.33
N$X.602  (via drill 0.2)  (1 unrouted)
  Bottom 0.2: 60.53,17.96 61.08,17.42
  other vias: 61.13,17.33
N$X.603  (via drill 0.2)  (1 unrouted)
  Bottom 0.2: 62.2,17.96 62.74,17.42
  other vias: 62.79,17.33
N$X.604  (via drill 0.2)  (1 unrouted)
  Bottom 0.2: 63.94,17.96 64.48,17.42
  other vias: 64.53,17.33
N$X.605  (via drill 0.2)  (1 unrouted)
  Bottom 0.2: 64.02,20.46 64.56,19.91
  other vias: 64.53,19.9
N$X.606  (via drill 0.2)  (1 unrouted)
  Bottom 0.2: 62.23,20.54 62.78,19.99
  other vias: 62.83,19.9
N$X.607  (via drill 0.2)  (1 unrouted)
  Bottom 0.2: 65.7,20.55 66.24,20
  other vias: 66.3,19.91
N$X.608  (via drill 0.2)  (1 unrouted)
  Bottom 0.2: 65.86,23.12 66.4,22.57
  other vias: 66.45,22.48
N$X.609  (via drill 0.2)  (1 unrouted)
  Bottom 0.2: 63.98,23.12 64.52,22.57
  other vias: 64.57,22.48
N$X.610  (via drill 0.2)  (1 unrouted)
  Bottom 0.2: 58.57,25.73 59.12,25.19
  other vias: 59.17,25.09
N$X.611  (via drill 0.2)  (1 unrouted)
  Bottom 0.2: 60.43,25.71 60.98,25.17
  other vias: 61.03,25.07
N$X.612  (via drill 0.2)  (1 unrouted)
  Bottom 0.2: 62.17,25.69 62.72,25.15
  other vias: 62.77,25.05
N$X.613  (via drill 0.2)  (1 unrouted)
  Bottom 0.2: 64,25.73 64.54,25.19
  other vias: 64.59,25.09
N$X.614  (via drill 0.2)  (1 unrouted)
  Bottom 0.2: 65.86,25.75 66.4,25.21
  other vias: 66.45,25.11
N$X.615  (via drill 0.2)  (1 unrouted)
  Bottom 0.2: 62.17,23.12 62.72,22.57
  other vias: 62.77,22.48
N$X.616  (via drill 0.2)  (1 unrouted)
  Bottom 0.2: 60.45,23.14 61,22.59
  other vias: 61.05,22.5
N$X.617  (via drill 0.2)  (1 unrouted)
  Bottom 0.2: 58.59,23.1 59.14,22.55
  other vias: 59.19,22.46
N$X.618  (via drill 0.2)  (1 unrouted)
  Bottom 0.2: 58.61,20.51 59.16,19.96
  other vias: 59.21,19.87
N$X.619  (via drill 0.2)  (1 unrouted)
  Bottom 0.2: 60.41,20.55 60.96,20
  other vias: 61.01,19.91
N$X.621  (via drill 0.2)  (1 unrouted)
  Bottom 0.2: 65.7,17.96 66.24,17.41
  other vias: 66.3,17.32
N$X.622  (via drill 0.2)  (1 unrouted)
  Bottom 0.2: 65.8,31.3 66.34,30.76
  other vias: 66.39,30.66
N$X.623  (via drill 0.2)  (1 unrouted)
  Bottom 0.2: 83.99,33.2 83.47,33.71 83.15,33.71
  other vias: 84.03,33.18
N$X.624  (via drill 0.2)  (1 unrouted)
  Bottom 0.2: 65.88,28.57 66.42,28.03
  other vias: 66.47,27.93
N$X.625  (via drill 0.2)  (1 unrouted)
  Bottom 0.2: 84.05,38.39 83.2,39.23 83.17,39.23
  other vias: 84.04,38.45
N$X.626  (via drill 0.2)
  Bottom 0.2: 83.97,41.08 83.52,41.78
  Bottom 0.5: v84.02,41.03 83.97,41.08
N$X.627  (via drill 0.2)  (1 unrouted)
  Bottom 0.2: 84.07,43.83 83.97,43.73 83.42,44.28
  other vias: 84.07,43.63
N$X.628  (via drill 0.2)
  Bottom 0.2: v84.01,46.19 83.81,46.19 83.27,46.83
N$X.629  (via drill 0.2)  (1 unrouted)
  Bottom 0.2: 64.02,31.22 64.56,30.68
  other vias: 64.61,30.58
N$X.630  (via drill 0.2)  (1 unrouted)
  Bottom 0.2: 62.16,31.22 62.7,30.68
  other vias: 62.75,30.58
N$X.631  (via drill 0.2)  (1 unrouted)
  Bottom 0.2: 60.38,31.22 60.92,30.68
  other vias: 60.97,30.58
N$X.632  (via drill 0.2)  (1 unrouted)
  Bottom 0.2: 58.52,31.3 59.06,30.76
  other vias: 59.11,30.66
N$X.633  (via drill 0.2)  (1 unrouted)
  Bottom 0.2: 62.23,28.41 62.78,27.87
  other vias: 62.83,27.77
N$X.634  (via drill 0.2)  (1 unrouted)
  Bottom 0.2: 64.02,28.53 64.56,27.99
  other vias: 64.61,27.89
N$X.635  (via drill 0.2)  (1 unrouted)
  Bottom 0.2: 60.41,28.49 60.96,27.95
  other vias: 61.01,27.85
N$X.636  (via drill 0.2)  (1 unrouted)
  Bottom 0.2: 58.59,28.53 59.14,27.99
  other vias: 59.19,27.89
N$X.637  (via drill 0.2)  (1 unrouted)
  Bottom 0.2: 60.35,41.71 60.9,41.16
  other vias: 60.95,41.07
N$X.638  (via drill 0.2)  (1 unrouted)
  Bottom 0.2: 62.2,41.69 62.74,41.15
  other vias: 62.79,41.05
N$X.639  (via drill 0.2)  (1 unrouted)
  Bottom 0.2: 64.03,41.69 64.58,41.15
  other vias: 64.63,41.05
N$X.640  (via drill 0.2)  (1 unrouted)
  Bottom 0.2: 65.88,39.08 66.42,38.53
  other vias: 66.47,38.44
N$X.641  (via drill 0.2)  (1 unrouted)
  Bottom 0.2: 65.82,41.65 66.36,41.11
  other vias: 66.41,41.01
N$X.642  (via drill 0.2)  (1 unrouted)
  Bottom 0.2: 63.96,39.1 64.5,38.55
  other vias: 64.55,38.46
N$X.643  (via drill 0.2)  (1 unrouted)
  Bottom 0.2: 62.16,39.08 62.7,38.53
  other vias: 62.75,38.44
N$X.644  (via drill 0.2)  (1 unrouted)
  Bottom 0.2: 60.41,39.04 60.96,38.49
  other vias: 61.01,38.4
N$X.645  (via drill 0.2)  (1 unrouted)
  Bottom 0.2: 58.57,39.1 59.12,38.55
  other vias: 59.17,38.46
N$X.646  (via drill 0.2)  (1 unrouted)
  Bottom 0.2: 58.55,36.47 59.1,35.92
  other vias: 59.15,35.83
N$X.647  (via drill 0.2)  (1 unrouted)
  Bottom 0.2: 60.41,36.47 60.96,35.92
  other vias: 61.01,35.83
N$X.648  (via drill 0.2)  (1 unrouted)
  Bottom 0.2: 62.2,36.47 62.74,35.92
  other vias: 62.79,35.83
N$X.649  (via drill 0.2)  (1 unrouted)
  Bottom 0.2: 63.98,36.43 64.52,35.88
  other vias: 64.57,35.79
N$X.650  (via drill 0.2)  (1 unrouted)
  Bottom 0.2: 65.82,36.53 66.36,35.98
  other vias: 66.41,35.89
N$X.651  (via drill 0.2)  (1 unrouted)
  Bottom 0.2: 65.76,33.8 66.3,33.25
  other vias: 66.36,33.16
N$X.652  (via drill 0.2)  (1 unrouted)
  Bottom 0.2: 63.98,33.8 64.52,33.25
  other vias: 64.57,33.16
N$X.653  (via drill 0.2)  (1 unrouted)
  Bottom 0.2: 62.17,33.78 62.72,33.23
  other vias: 62.77,33.14
N$X.654  (via drill 0.2)  (1 unrouted)
  Bottom 0.2: 60.31,33.8 60.86,33.25
  other vias: 60.91,33.16
N$X.655  (via drill 0.2)  (1 unrouted)
  Bottom 0.2: 58.57,33.81 59.12,33.27
  other vias: 59.17,33.18
N$X.656  (via drill 0.2)  (1 unrouted)
  Bottom 0.2: 82.25,38.45 81.67,39.03 81.67,39.06
  other vias: 82.27,38.46
N$X.657  (via drill 0.2)
  Bottom 0.2: v82.33,41.02 82.17,41.18 81.77,41.88
N$X.658  (via drill 0.2)  (1 unrouted)
  Bottom 0.2: 81.72,44.23 82.27,43.68
  other vias: 82.3,43.64
N$X.659  (via drill 0.2)  (1 unrouted)
  Bottom 0.2: 108.47,35.82 107.93,36.36 107.58,36.36
  other vias: 108.43,35.8
N$X.660  (via drill 0.2)  (1 unrouted)
  Bottom 0.2: 55.03,70.48 55.58,69.94
  other vias: 55.63,69.85
N$X.661  (via drill 0.2)  (1 unrouted)
  Bottom 0.2: 56.77,70.48 57.32,69.94
  other vias: 57.37,69.85
N$X.662  (via drill 0.2)  (1 unrouted)
  Bottom 0.2: 58.52,70.44 59.06,69.9
  other vias: 59.11,69.81
N$X.663  (via drill 0.2)  (1 unrouted)
  Bottom 0.2: 60.38,70.48 60.92,69.94
  other vias: 60.97,69.85
N$X.664  (via drill 0.2)  (1 unrouted)
  Bottom 0.2: 62.27,70.48 62.82,69.94
  other vias: 62.87,69.85
N$X.665  (via drill 0.2)  (1 unrouted)
  Bottom 0.2: 63.94,70.48 64.48,69.94
  other vias: 64.53,69.85
N$X.666  (via drill 0.2)  (1 unrouted)
  Bottom 0.2: 65.84,70.52 66.38,69.98
  other vias: 66.43,69.89
N$X.667  (via drill 0.2)  (1 unrouted)
  Bottom 0.2: 58.55,67.79 59.1,67.25
  other vias: 59.15,67.16
N$X.668  (via drill 0.2)  (1 unrouted)
  Bottom 0.2: 58.55,65.18 59.1,64.64
  other vias: 59.15,64.54
N$X.669  (via drill 0.2)  (1 unrouted)
  Bottom 0.2: 59.22,61.98 58.67,62.53
  other vias: 59.27,61.89
N$X.670  (via drill 0.2)  (1 unrouted)
  Bottom 0.2: 58.59,60 59.14,59.45
  other vias: 59.19,59.36
N$X.671  (via drill 0.2)  (1 unrouted)
  Bottom 0.2: 58.63,57.23 59.18,56.68
  other vias: 59.23,56.59
N$X.672  (via drill 0.2)  (1 unrouted)
  Bottom 0.2: 60.96,56.68 60.41,57.23
  other vias: 61.01,56.59
N$X.673  (via drill 0.2)  (1 unrouted)
  Bottom 0.2: 61,59.45 60.45,60
  other vias: 61.05,59.36
N$X.674  (via drill 0.2)  (1 unrouted)
  Bottom 0.2: 60.96,62.06 60.41,62.61
  other vias: 61.01,61.97
N$X.675  (via drill 0.2)  (1 unrouted)
  Bottom 0.2: 60.88,64.67 60.34,65.22
  other vias: 60.93,64.58
N$X.676  (via drill 0.2)  (1 unrouted)
  Bottom 0.2: 60.92,67.25 60.38,67.79
  other vias: 60.97,67.16
N$X.677  (via drill 0.2)  (1 unrouted)
  Bottom 0.2: 62.7,67.25 62.16,67.79
  other vias: 62.75,67.16
N$X.678  (via drill 0.2)  (1 unrouted)
  Bottom 0.2: 64.52,67.21 63.98,67.75
  other vias: 64.57,67.12
N$X.679  (via drill 0.2)  (1 unrouted)
  Bottom 0.2: 62.74,64.56 62.2,65.1
  other vias: 62.79,64.46
N$X.680  (via drill 0.2)  (1 unrouted)
  Bottom 0.2: 64.48,64.6 63.94,65.14
  other vias: 64.53,64.5
N$X.681  (via drill 0.2)  (1 unrouted)
  Bottom 0.2: 64.52,62.02 63.98,62.57
  other vias: 64.57,61.93
N$X.682  (via drill 0.2)  (1 unrouted)
  Bottom 0.2: 62.82,61.98 62.27,62.53
  other vias: 62.87,61.89
N$X.683  (via drill 0.2)  (1 unrouted)
  Bottom 0.2: 62.82,59.41 62.27,59.96
  other vias: 62.87,59.32
N$X.684  (via drill 0.2)  (1 unrouted)
  Bottom 0.2: 64.52,59.41 63.98,59.96
  other vias: 64.57,59.32
N$X.685  (via drill 0.2)  (1 unrouted)
  Bottom 0.2: 80.52,33.12 79.95,33.69 79.95,33.82
  other vias: 80.54,33.15
N$X.686  (via drill 0.2)  (1 unrouted)
  Bottom 0.2: 80.58,35.75 79.88,36.46
  other vias: 80.56,35.79
N$X.687  (via drill 0.2)  (1 unrouted)
  Bottom 0.2: 80.5,38.45 79.92,39.03 79.92,39.22
  other vias: 80.52,38.47
N$X.688  (via drill 0.2)  (1 unrouted)
  Bottom 0.2: 80.55,40.99 79.91,41.63 79.69,41.63
  other vias: 80.52,41.03
N$X.689  (via drill 0.2)  (1 unrouted)
  Bottom 0.2: 80.5,43.63 79.9,44.23 79.75,44.23
  other vias: 80.52,43.63
N$X.690  (via drill 0.2)  (1 unrouted)
  Bottom 0.2: 110.27,35.82 109.72,36.36 109.37,36.36
  other vias: 110.22,35.8
N$X.691  (via drill 0.2)  (1 unrouted)
  Bottom 0.2: 64.56,56.72 64.02,57.27
  other vias: 64.61,56.63
N$X.692  (via drill 0.2)  (1 unrouted)
  Bottom 0.2: 62.74,56.72 62.2,57.27
  other vias: 62.79,56.63
N$X.693  (via drill 0.2)  (1 unrouted)
  Bottom 0.2: 115.3,44.31 115.84,43.76
  other vias: 115.9,43.67
N$X.694  (via drill 0.2)  (1 unrouted)
  Bottom 0.2: 58.67,54.53 59.22,53.99
  other vias: 59.27,53.9
N$X.695  (via drill 0.2)  (1 unrouted)
  Bottom 0.2: 60.96,54.03 60.41,54.57
  other vias: 61.01,53.94
N$X.696  (via drill 0.2)  (1 unrouted)
  Bottom 0.2: 62.12,54.53 62.66,53.99
  other vias: 62.71,53.9
N$X.697  (via drill 0.2)  (1 unrouted)
  Bottom 0.2: 63.94,54.49 64.48,53.95
  other vias: 64.53,53.86
N$X.698  (via drill 0.2)  (1 unrouted)
  Bottom 0.2: 65.76,54.53 66.3,53.99
  other vias: 66.36,53.9
N$X.699  (via drill 0.2)  (1 unrouted)
  Bottom 0.2: 65.76,51.96 66.3,51.42
  other vias: 66.36,51.32
N$X.700  (via drill 0.2)  (1 unrouted)
  Bottom 0.2: 63.98,51.96 64.52,51.42
  other vias: 64.57,51.32
N$X.701  (via drill 0.2)  (1 unrouted)
  Bottom 0.2: 62.2,51.92 62.74,51.38
  other vias: 62.79,51.28
N$X.702  (via drill 0.2)  (1 unrouted)
  Bottom 0.2: 58.55,51.96 59.1,51.42
  other vias: 59.15,51.32
N$X.703  (via drill 0.2)  (1 unrouted)
  Bottom 0.2: 60.41,51.96 60.96,51.42
  other vias: 61.01,51.32
N$X.704  (via drill 0.2)  (1 unrouted)
  Bottom 0.2: 60.38,49.39 60.92,48.84
  other vias: 60.97,48.75
N$X.705  (via drill 0.2)  (1 unrouted)
  Bottom 0.2: 62.2,49.39 62.74,48.84
  other vias: 62.79,48.75
N$X.706  (via drill 0.2)  (1 unrouted)
  Bottom 0.2: 63.94,49.39 64.48,48.84
  other vias: 64.53,48.75
N$X.707  (via drill 0.2)  (1 unrouted)
  Bottom 0.2: 65.8,49.35 66.34,48.8
  other vias: 66.39,48.71
N$X.708  (via drill 0.2)  (1 unrouted)
  Bottom 0.2: 60.41,46.78 60.96,46.23
  other vias: 61.01,46.14
N$X.709  (via drill 0.2)  (1 unrouted)
  Bottom 0.2: 62.2,46.78 62.74,46.23
  other vias: 62.79,46.14
N$X.710  (via drill 0.2)  (1 unrouted)
  Bottom 0.2: 64.02,46.82 64.56,46.27
  other vias: 64.61,46.18
N$X.711  (via drill 0.2)  (1 unrouted)
  Bottom 0.2: 63.98,44.2 64.52,43.66
  other vias: 64.57,43.57
N$X.712  (via drill 0.2)  (1 unrouted)
  Bottom 0.2: 62.2,44.2 62.74,43.66
  other vias: 62.79,43.57
N$X.713  (via drill 0.2)  (1 unrouted)
  Bottom 0.2: 38.8,12.8 39.35,12.26
  other vias: 39.4,12.16
N$X.714  (via drill 0.2)  (1 unrouted)
  Bottom 0.2: 38.78,15.49 39.33,14.95
  other vias: 39.38,14.85
N$X.715  (via drill 0.2)  (1 unrouted)
  Bottom 0.2: 40.59,15.48 41.14,14.93
  other vias: 41.19,14.84
N$X.716  (via drill 0.2)  (1 unrouted)
  Bottom 0.2: v78.8,33.17 78.03,33.95 77.91,33.95
N$X.717  (via drill 0.2)  (1 unrouted)
  Bottom 0.2: 78.83,35.84 78.03,36.63 78.03,36.64
  other vias: 78.81,35.83
N$X.718  (via drill 0.2)  (1 unrouted)
  Bottom 0.2: 78.77,38.42 78.06,39.13 77.86,39.13
  other vias: 78.79,38.46
N$X.719  (via drill 0.2)  (1 unrouted)
  Bottom 0.2: 78.78,41.04 78.07,41.76 78.05,41.76
  other vias: 78.73,41.03
N$X.720  (via drill 0.2)  (1 unrouted)
  Bottom 0.2: 78.85,43.69 78.25,44.28 78.05,44.28
  other vias: 78.82,43.63
N$X.721  (via drill 0.2)  (1 unrouted)
  Bottom 0.2: 112.05,35.8 111.5,36.35 111.16,36.35
  other vias: 112,35.78
N$X.722  (via drill 0.2)  (1 unrouted)
  Bottom 0.2: 42.39,15.49 42.93,14.95
  other vias: 42.99,14.85
N$X.723  (via drill 0.2)  (1 unrouted)
  Bottom 0.2: 29.77,15.49 30.31,14.95
  other vias: 30.37,14.85
N$X.724  (via drill 0.2)  (1 unrouted)
  Bottom 0.2: 31.59,15.46 32.14,14.92
  other vias: 32.19,14.82
N$X.725  (via drill 0.2)  (1 unrouted)
  Bottom 0.2: 33.37,15.43 33.92,14.88
  other vias: 33.97,14.79
N$X.726  (via drill 0.2)  (1 unrouted)
  Bottom 0.2: 113.15,33.84 113.69,33.3
  other vias: 113.75,33.2
N$X.727  (via drill 0.2)  (1 unrouted)
  Bottom 0.2: 36.96,15.44 37.5,14.9
  other vias: 37.56,14.81
N$X.728  (via drill 0.2)  (1 unrouted)
  Bottom 0.2: 29.77,12.83 30.31,12.29
  other vias: 30.37,12.2
N$X.729  (via drill 0.2)  (1 unrouted)
  Bottom 0.2: 31.59,12.85 32.14,12.3
  other vias: 32.19,12.21
N$X.730  (via drill 0.2)  (1 unrouted)
  Bottom 0.2: 33.37,12.8 33.92,12.26
  other vias: 33.97,12.16
N$X.731  (via drill 0.2)  (1 unrouted)
  Bottom 0.2: 35.23,12.83 35.77,12.29
  other vias: 35.83,12.2
N$X.732  (via drill 0.2)  (1 unrouted)
  Bottom 0.2: 36.96,12.82 37.5,12.27
  other vias: 37.56,12.18
N$X.733  (via drill 0.2)  (1 unrouted)
  Bottom 0.2: 65.74,44.31 66.28,43.76
  other vias: 66.34,43.67
N$X.734  (via drill 0.2)  (1 unrouted)
  Bottom 0.2: 65.71,46.82 66.25,46.28
  other vias: 66.3,46.18
N$X.735  (via drill 0.2)  (1 unrouted)
  Bottom 0.2: 65.88,57.23 66.43,56.69
  other vias: 66.48,56.59
N$X.736  (via drill 0.2)  (1 unrouted)
  Bottom 0.2: 65.91,59.99 66.46,59.44
  other vias: 66.51,59.35
N$X.737  (via drill 0.2)  (1 unrouted)
  Bottom 0.2: 65.9,62.58 66.44,62.04
  other vias: 66.5,61.94
N$X.738  (via drill 0.2)  (1 unrouted)
  Bottom 0.2: 65.93,65.19 66.47,64.65
  other vias: 66.53,64.55
N$X.739  (via drill 0.2)  (1 unrouted)
  Bottom 0.2: 65.9,67.79 66.44,67.24
  other vias: 66.5,67.15
N$X.740  (via drill 0.2)  (1 unrouted)
  Bottom 0.2: 113.09,31.22 113.64,30.68
  other vias: 113.69,30.58
N$X.741  (via drill 0.2)  (1 unrouted)
  Bottom 0.2: 113.17,28.53 113.72,27.98
  other vias: 113.77,27.89
N$X.742  (via drill 0.2)  (1 unrouted)
  Bottom 0.2: 113.07,25.75 113.61,25.2
  other vias: 113.66,25.11
N$X.743  (via drill 0.2)  (1 unrouted)
  Bottom 0.2: 113.07,23.1 113.61,22.56
  other vias: 113.66,22.46
N$X.744
  Bottom 0.2: 66,23.04 65.66,23.04
N$X.745  (via drill 0.2)  (1 unrouted)
  Bottom 0.2: 113.09,20.51 113.64,19.97
  other vias: 113.69,19.87
N$X.746  (via drill 0.2)  (1 unrouted)
  Bottom 0.2: 113.15,18.11 113.69,17.56
  other vias: 113.75,17.47
N$X.747  (via drill 0.2)  (1 unrouted)
  Bottom 0.2: 77.05,33.16 76.31,33.9 76.3,33.9
  other vias: 77.04,33.2
N$X.748  (via drill 0.2)  (1 unrouted)
  Bottom 0.2: 77.01,35.79 76.38,36.42 76.38,36.55
  other vias: 77.03,35.82
N$X.749  (via drill 0.2)  (1 unrouted)
  Bottom 0.2: 76.96,38.42 76.16,39.22 76.16,39.35
  other vias: 77,38.45
N$X.750  (via drill 0.2)  (1 unrouted)
  Bottom 0.2: 77.03,41.02 76.27,41.78 76.09,41.78
  other vias: 77.07,41.03
N$X.751  (via drill 0.2)  (1 unrouted)
  Bottom 0.2: 77.08,43.65 76.43,44.29 76.13,44.29
  other vias: 77.07,43.63
N$X.752  (via drill 0.2)  (1 unrouted)
  Bottom 0.2: 108.55,33.14 108.01,33.68 107.66,33.68
  other vias: 108.51,33.16
N$X.753  (via drill 0.2)  (1 unrouted)
  Bottom 0.2: 113.12,15.44 113.66,14.89
  other vias: 113.72,14.8
N$X.754  (via drill 0.2)  (1 unrouted)
  Bottom 0.2: 113.07,12.85 113.61,12.3
  other vias: 113.66,12.21
N$X.755  (via drill 0.2)  (1 unrouted)
  Bottom 0.2: 113.07,10.23 113.61,9.68
  other vias: 113.66,9.59
N$X.756  (via drill 0.2)  (1 unrouted)
  Bottom 0.2: 113.2,7.61 113.75,7.07
  other vias: 113.8,6.97
N$X.757  (via drill 0.2)  (1 unrouted)
  Bottom 0.2: 113.09,4.94 113.64,4.4
  other vias: 113.69,4.3
N$X.758  (via drill 0.2)  (1 unrouted)
  Top 0.8: 113.81,85.01 113.81,1.75
  Bottom 0.2: 113.09,2.43 113.64,1.89
  other vias: 113.69,1.79
N$X.759  (via drill 0.2)  (1 unrouted)
  Bottom 0.2: 113.83,59.5 113.28,60.04
  other vias: 113.88,59.4
N$X.760  (via drill 0.2)  (1 unrouted)
  Bottom 0.2: 113.8,56.77 113.25,57.31
  other vias: 113.85,56.68
N$X.761  (via drill 0.2)  (1 unrouted)
  Bottom 0.2: 113.42,70.48 113.96,69.94
  other vias: 114.02,69.84
N$X.762  (via drill 0.2)  (1 unrouted)
  Bottom 0.2: 113.31,73.18 113.85,72.64
  other vias: 113.91,72.54
N$X.763  (via drill 0.2)  (1 unrouted)
  Bottom 0.2: 113.31,75.8 113.85,75.25
  other vias: 113.91,75.16
N$X.764  (via drill 0.2)  (1 unrouted)
  Bottom 0.2: 113.36,78.12 113.91,77.57
  other vias: 113.96,77.48
N$X.765  (via drill 0.2)  (1 unrouted)
  Bottom 0.2: 113.31,80.71 113.85,80.16
  other vias: 113.91,80.07
N$X.766  (via drill 0.2)  (1 unrouted)
  Bottom 0.2: 113.32,83.34 113.86,82.79
  other vias: 113.92,82.7
N$X.768  (1 unrouted)
N$X.770  (via drill 0.2)
  Bottom 0.2: 115.27,28.57 115.82,28.02
  other vias: 115.87,27.93
N$X.773  (1 unrouted)
N$X.774  (via drill 0.2)  (1 unrouted)
  Bottom 0.2: 115.29,78.14 115.84,77.59
  other vias: 115.89,77.5
N$X.775  (via drill 0.2)  (1 unrouted)
  Bottom 0.2: 115.24,80.73 115.78,80.18
  other vias: 115.84,80.09
N$X.776  (via drill 0.2)  (1 unrouted)
  Bottom 0.2: 115.25,83.36 115.79,82.81
  other vias: 115.85,82.72
N$X.778  (via drill 0.2)  (1 unrouted)
  Bottom 0.2: 75.27,33.15 74.55,33.86 74.37,33.86
  other vias: 75.3,33.16
N$X.779  (via drill 0.2)  (1 unrouted)
  Bottom 0.2: 75.29,35.77 74.53,36.54 74.36,36.54
  other vias: 75.3,35.79
N$X.780  (via drill 0.2)  (1 unrouted)
  Bottom 0.2: 75.31,38.43 74.56,39.18 74.16,39.18
  other vias: 75.31,38.4
N$X.781  (via drill 0.2)  (1 unrouted)
  Bottom 0.2: v75.25,41.03 74.61,41.68 74.55,41.68
N$X.782  (via drill 0.2)  (1 unrouted)
  Bottom 0.2: 75.29,43.62 74.53,44.39 74.53,44.45
  other vias: 75.27,43.63
N$X.783  (via drill 0.2)  (1 unrouted)
  Bottom 0.2: 110.29,33.16 109.75,33.71 109.39,33.71
  other vias: 110.25,33.14
N$X.784  (1 unrouted)
N$X.786  (via drill 0.2)  (1 unrouted)
  Bottom 0.2: 115.31,70.45 115.86,69.9
  other vias: 115.91,69.81
N$X.787  (via drill 0.2)  (1 unrouted)
  Bottom 0.2: 115.26,73.04 115.8,72.49
  other vias: 115.86,72.4
N$X.788  (via drill 0.2)  (1 unrouted)
  Bottom 0.2: 115.27,75.67 115.81,75.12
  other vias: 115.87,75.03
N$X.790  (1 unrouted)
N$X.791  (via drill 0.2)  (1 unrouted)
  Bottom 0.2: 115.86,62.08 115.31,62.63
  other vias: 115.91,61.99
N$X.792  (via drill 0.2)  (1 unrouted)
  Bottom 0.2: 115.8,64.67 115.26,65.22
  other vias: 115.86,64.58
N$X.793  (via drill 0.2)  (1 unrouted)
  Bottom 0.2: 115.27,67.85 115.81,67.3
  other vias: 115.87,67.21
N$X.794  (via drill 0.2)  (1 unrouted)
  Bottom 0.2: 115.88,54.25 115.33,54.8
  other vias: 115.93,54.02
N$X.795  (via drill 0.2)  (1 unrouted)
  Bottom 0.2: 115.82,56.84 115.28,57.39
  other vias: 115.88,56.66
N$X.796  (via drill 0.2)  (1 unrouted)
  Bottom 0.2: 115.83,59.47 115.29,60.02
  other vias: 115.89,59.38
N$X.798  (via drill 0.2)  (1 unrouted)
  Bottom 0.2: 115.3,51.98 115.85,51.43
  other vias: 115.9,51.34
N$X.800  (via drill 0.2)  (1 unrouted)
  Bottom 0.2: 115.32,41.77 115.87,41.22
  other vias: 115.92,41.13
N$X.801  (via drill 0.2)
  Bottom 0.2: 115.27,25.76 115.82,25.21
  other vias: 115.87,25.12
N$X.803  (via drill 0.2)  (1 unrouted)
  Bottom 0.2: 115.28,49.37 115.82,48.82
  other vias: 115.88,48.73
N$X.805  (via drill 0.2)  (1 unrouted)
  Bottom 0.2: 115.3,39.16 115.84,38.61
  other vias: 115.9,38.52
N$X.807  (via drill 0.2)  (1 unrouted)
  Bottom 0.2: 115.27,36.47 115.82,35.92
  other vias: 115.87,35.83
N$X.809  (via drill 0.2)  (1 unrouted)
  Bottom 0.2: 73.5,33.2 72.78,33.92 72.66,33.92
  other vias: 73.49,33.16
N$X.810  (via drill 0.2)  (1 unrouted)
  Bottom 0.2: 73.52,35.77 72.81,36.47 72.66,36.47
  other vias: 73.53,35.81
N$X.811  (via drill 0.2)  (1 unrouted)
  Bottom 0.2: 73.53,38.45 72.98,39 72.98,39.04
  other vias: 73.53,38.43
N$X.812  (via drill 0.2)  (1 unrouted)
  Bottom 0.2: v73.53,41.04 72.92,41.65 72.8,41.65
N$X.813  (via drill 0.2)  (1 unrouted)
  Bottom 0.2: 73.49,43.69 72.87,44.31 72.86,44.31
  other vias: 73.47,43.63
N$X.814  (via drill 0.2)  (1 unrouted)
  Bottom 0.2: 112.03,33.19 111.48,33.73 111.13,33.73
  other vias: 111.98,33.17
N$X.815  (via drill 0.2)  (1 unrouted)
  Bottom 0.2: 115.25,33.86 115.79,33.31
  other vias: 115.85,33.22
N$X.817  (via drill 0.2)  (1 unrouted)
  Bottom 0.2: 115.27,31.27 115.82,30.72
  other vias: 115.87,30.63
N$X.818  (via drill 0.2)
  Bottom 0.2: 115.27,23.13 115.82,22.58
  other vias: 115.87,22.49
N$X.819  (1 unrouted)
N$X.821  (via drill 0.2)
  Bottom 0.2: 115.27,20.55 115.82,20
  other vias: 115.87,19.91
N$X.823  (via drill 0.2)
  Bottom 0.2: 115.23,18.11 115.78,17.56
  other vias: 115.83,17.47
N$X.825  (via drill 0.2)
  Bottom 0.2: 115.23,15.54 115.78,14.99
  other vias: 115.83,14.9
N$X.827  (via drill 0.2)
  Bottom 0.2: 115.23,12.87 115.78,12.32
  other vias: 115.83,12.23
N$X.829  (via drill 0.2)
  Bottom 0.2: 115.23,10.29 115.78,9.74
  other vias: 115.83,9.65
N$X.831  (via drill 0.2)
  Bottom 0.2: 115.18,7.66 115.73,7.11
  other vias: 115.78,7.02
N$X.833  (via drill 0.2)
  Bottom 0.2: 115.13,5.04 115.68,4.49
  other vias: 115.73,4.4
N$X.835  (via drill 0.2)
  Top 0.8: 115.72,1.73 115.72,84.73
  Bottom 0.2: 115.13,2.46 115.68,1.91
  other vias: 115.73,1.82
N$X.840  (via drill 0.2)  (1 unrouted)
  Bottom 0.2: v71.75,33.18 71.12,33.82 71.03,33.86
N$X.841  (via drill 0.2)  (1 unrouted)
  Bottom 0.2: 71.78,35.79 71.05,36.52 70.75,36.52
  other vias: 71.78,35.8
N$X.842  (via drill 0.2)  (1 unrouted)
  Bottom 0.2: 71.77,38.42 71.09,39.09 70.72,39.09
  other vias: 71.75,38.41
N$X.843  (via drill 0.2)  (1 unrouted)
  Bottom 0.2: 71.75,41.06 71.06,41.74 70.75,41.78
  other vias: 71.77,41.04
N$X.844  (via drill 0.2)  (1 unrouted)
  Bottom 0.2: 71.7,43.66 71.21,44.31 70.97,44.31
  other vias: 71.72,43.65
N$X.871  (via drill 0.2)  (1 unrouted)
  Bottom 0.2: v70,33.17 69.41,33.77 69.41,33.82
N$X.872  (via drill 0.2)  (1 unrouted)
  Bottom 0.2: 69.98,35.79 69.3,36.47 69.3,36.56
  other vias: 69.97,35.8
N$X.873  (via drill 0.2)  (1 unrouted)
  Bottom 0.2: 69.97,38.35 69.39,38.92 69.39,39.14
  other vias: 70.01,38.4
N$X.874  (via drill 0.2)  (1 unrouted)
  Bottom 0.2: 70.03,41.02 69.37,41.68 69.01,41.68
  other vias: 70.02,41.03
N$X.875
  Bottom 0.2: 68.8,44.49 69.2,44.49 70.05,43.63
N$X.876  (via drill 0.2)
  Bottom 0.2: v70.02,46.18 69.23,46.97 69.08,46.97
N$X.902  (via drill 0.2)  (1 unrouted)
  Bottom 0.2: 68.32,33.21 67.8,33.73 67.43,33.73
  other vias: 68.28,33.19
N$X.903  (via drill 0.2)  (1 unrouted)
  Bottom 0.2: 68.27,35.75 67.43,36.59 67.26,36.59
  other vias: 68.27,35.79
N$X.904  (via drill 0.2)  (1 unrouted)
  Bottom 0.2: 68.25,38.39 67.49,39.14 67.31,39.14
  other vias: 68.28,38.42
N$X.905  (via drill 0.2)  (1 unrouted)
  Bottom 0.2: 68.27,40.98 67.49,41.76 67.17,41.76
  other vias: 68.27,41.03
N$X.906  (via drill 0.2)  (1 unrouted)
  Bottom 0.2: 68.27,43.63 67.37,44.53 67.22,44.53
  other vias: 68.22,43.63
N$X.907  (via drill 0.2)  (1 unrouted)
  Bottom 0.2: 68.2,46.19 67.64,46.76 67.35,46.74
  other vias: 68.22,46.18
N$X.933
  Bottom 0.2: 65.7,33.99 65.56,33.99
N$X.934
  Bottom 0.2: 65.8,36.42 65.61,36.42
N$X.935
  Bottom 0.2: 65.84,39.06 65.48,39.06
N$X.938
  Bottom 0.2: 65.63,46.86 65.9,46.81
N$X.964
  Bottom 0.2: 63.81,33.84 64.16,33.84
N$X.965
  Bottom 0.2: 63.89,36.5 64.01,36.5
N$X.966
  Bottom 0.2: 63.77,39.14 63.99,39.14
N$X.967
  Bottom 0.2: 64.02,41.73 64.12,41.73
N$X.968
  Bottom 0.2: 63.97,44.28 64.12,44.28
N$X.995
  Bottom 0.2: 62.05,33.81 62.34,33.81
N$X.996
  Bottom 0.2: 61.95,36.45 62.27,36.45
N$X.997
  Bottom 0.2: 62.1,39.08 62.34,39.08
N$X.998
  Bottom 0.2: 62.37,41.68 62.37,41.63
N$X.1000
  Bottom 0.2: 62.17,46.88 62.27,46.88
N$X.1026
  Bottom 0.2: 60.44,34.05 59.95,34.05
N$X.1027
  Bottom 0.2: 60.48,36.54 60.21,36.54
N$X.1028
  Bottom 0.2: 60.44,39.24 60.25,39.24
N$X.1030  (via drill 0.2)  (1 unrouted)
  Bottom 0.2: 61.27,43.58 60.62,44.23 60.67,44.33
  other vias: 61.27,43.63
N$X.1057
  Bottom 0.2: 58.67,33.87 58.73,33.87
N$X.1061
  Bottom 0.2: 58.78,44.33 58.78,44.42
N$X.1120
  Bottom 0.2: 55.05,36.52 55.2,36.52
N$X.1389  (via drill 0.2)  (1 unrouted)
  Bottom 0.2: 28.24,75 27.7,75.54 27.34,75.54
  other vias: 28.57,74.94
N$X.1429  (via drill 0.2)  (1 unrouted)
  Bottom 0.2: v39.4,33.17 38.74,33.83 38.43,33.83
N$X.1430  (via drill 0.2)  (1 unrouted)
